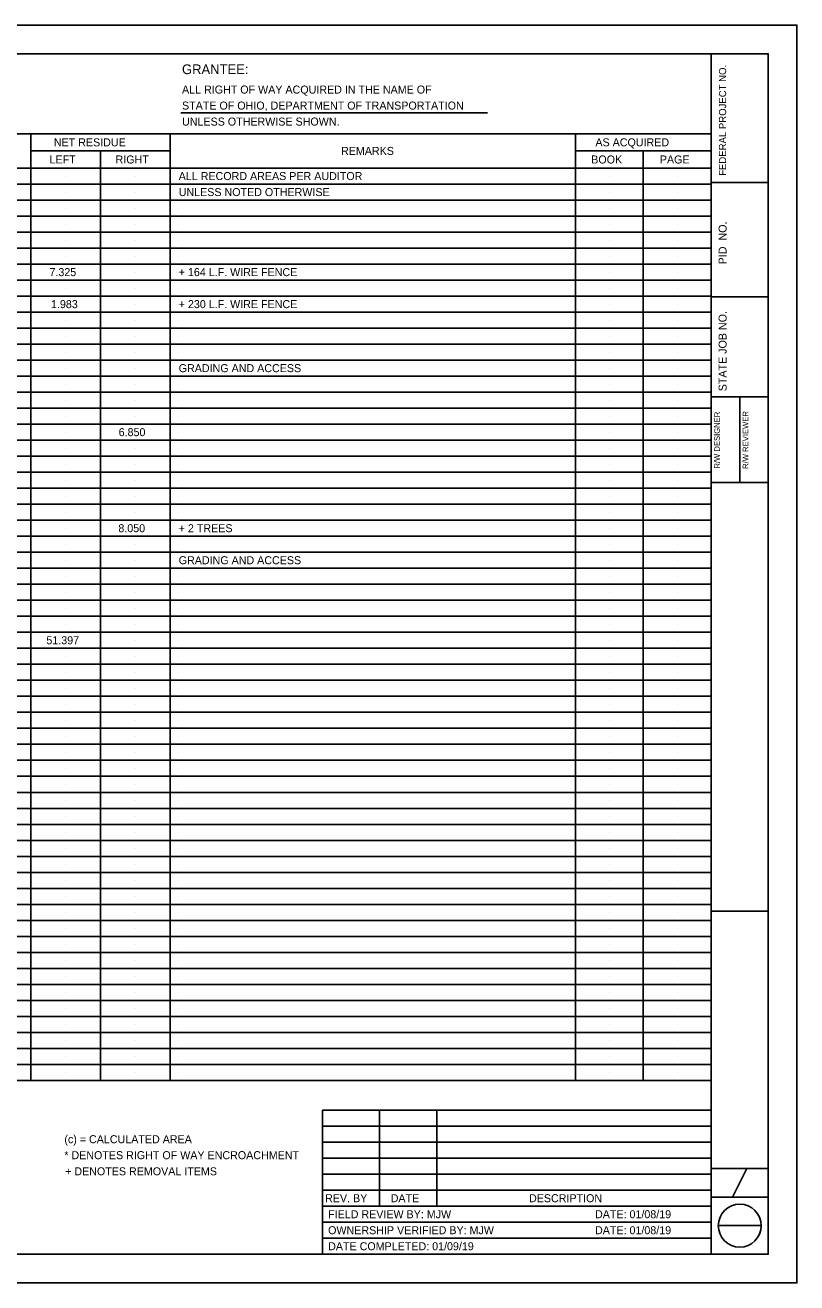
# Model space of a CAD drawing. Extents: x 1.1 to 35.1, y -0.9 to 21.1.
# Drawn here: x 21.58 to 35.08, y -0.86 to 21.14 of the extents above; entities that cross this region are included whole.
import ezdxf

# ---------------------------------------------------------------- set-up
doc = ezdxf.new("R2010")
doc.units = 0
for name, color, linetype in [('SH_Border', 7, 'Continuous'), ('SH_Cut_Line', 7, 'Continuous'), ('SH_Data', 7, 'Continuous'), ('SH_Text', 7, 'Continuous')]:
    doc.layers.add(name, color=color, linetype=linetype)

msp = doc.modelspace()

# ---------------------------------------------------------------- linework, layer by layer
at = {"layer": 'SH_Border'}
for p, q in [((33.585, -0.356), (33.585, 20.644)), ((33.585, 18.394), (34.585, 18.394)), ((33.585, 16.394), (34.585, 16.394)), ((33.585, 14.644), (34.585, 14.644)), ((34.085, 14.644), (34.085, 13.144)), ((33.585, 13.144), (34.585, 13.144)), ((33.585, 5.644), (34.585, 5.644)), ((33.585, 1.144), (34.585, 1.144)), ((34.21, 1.144), (33.96, 0.644)), ((33.585, 0.644), (34.585, 0.644))]:
    msp.add_line(p, q, dxfattribs=at)
msp.add_lwpolyline([(3.085, 20.644), (34.585, 20.644), (34.585, -0.356), (3.085, -0.356)], close=True, dxfattribs=at)
at = {"layer": 'SH_Cut_Line'}
msp.add_lwpolyline([(1.085, -0.856), (35.085, -0.856), (35.085, 21.144), (1.085, 21.144)], close=True, dxfattribs=at)
at = {"layer": 'SH_Data'}
for p, q in [((3.085, 19.244), (33.585, 19.244)), ((21.678, 19.244), (21.678, 2.684)), ((24.116, 19.244), (24.116, 2.684)), ((31.209, 19.244), (31.209, 2.684)), ((21.678, 18.944), (24.116, 18.944)), ((22.897, 18.944), (22.897, 2.684)), ((31.209, 18.944), (33.585, 18.944)), ((32.397, 18.944), (32.397, 2.684)), ((3.085, 18.644), (33.585, 18.644)), ((22.288, 18.504), (22.288, 18.504)), ((23.506, 18.504), (23.506, 18.504)), ((24.266, 18.504), (24.266, 18.504)), ((31.803, 18.504), (31.803, 18.504)), ((32.991, 18.504), (32.991, 18.504)), ((3.085, 18.364), (33.585, 18.364)), ((3.085, 18.084), (33.585, 18.084)), ((22.288, 18.224), (22.288, 18.224)), ((23.506, 18.224), (23.506, 18.224)), ((24.266, 18.224), (24.266, 18.224)), ((31.803, 18.224), (31.803, 18.224)), ((32.991, 18.224), (32.991, 18.224)), ((22.288, 17.944), (22.288, 17.944)), ((23.506, 17.944), (23.506, 17.944)), ((24.266, 17.944), (24.266, 17.944)), ((31.803, 17.944), (31.803, 17.944)), ((32.991, 17.944), (32.991, 17.944)), ((3.085, 17.804), (33.585, 17.804)), ((22.288, 17.664), (22.288, 17.664)), ((23.506, 17.664), (23.506, 17.664)), ((24.266, 17.664), (24.266, 17.664)), ((31.803, 17.664), (31.803, 17.664)), ((32.991, 17.664), (32.991, 17.664)), ((3.085, 17.524), (33.585, 17.524)), ((22.288, 17.384), (22.288, 17.384)), ((23.506, 17.384), (23.506, 17.384)), ((24.266, 17.384), (24.266, 17.384)), ((31.803, 17.384), (31.803, 17.384)), ((32.991, 17.384), (32.991, 17.384)), ((3.085, 17.244), (33.585, 17.244)), ((3.085, 16.964), (33.585, 16.964)), ((22.288, 17.104), (22.288, 17.104)), ((23.506, 17.104), (23.506, 17.104)), ((24.266, 17.104), (24.266, 17.104)), ((31.803, 17.104), (31.803, 17.104)), ((32.991, 17.104), (32.991, 17.104)), ((22.288, 16.824), (22.288, 16.824)), ((23.506, 16.824), (23.506, 16.824)), ((24.266, 16.824), (24.266, 16.824)), ((31.803, 16.824), (31.803, 16.824)), ((32.991, 16.824), (32.991, 16.824)), ((3.085, 16.684), (33.585, 16.684)), ((22.288, 16.544), (22.288, 16.544)), ((23.506, 16.544), (23.506, 16.544)), ((24.266, 16.544), (24.266, 16.544)), ((31.803, 16.544), (31.803, 16.544)), ((32.991, 16.544), (32.991, 16.544)), ((3.085, 16.404), (33.585, 16.404)), ((3.085, 16.124), (33.585, 16.124)), ((22.288, 16.264), (22.288, 16.264)), ((23.506, 16.264), (23.506, 16.264)), ((24.266, 16.264), (24.266, 16.264)), ((31.803, 16.264), (31.803, 16.264)), ((32.991, 16.264), (32.991, 16.264)), ((3.085, 15.844), (33.585, 15.844)), ((22.288, 15.984), (22.288, 15.984)), ((23.506, 15.984), (23.506, 15.984)), ((24.266, 15.984), (24.266, 15.984)), ((31.803, 15.984), (31.803, 15.984)), ((32.991, 15.984), (32.991, 15.984)), ((22.288, 15.704), (22.288, 15.704)), ((23.506, 15.704), (23.506, 15.704)), ((24.266, 15.704), (24.266, 15.704)), ((31.803, 15.704), (31.803, 15.704)), ((32.991, 15.704), (32.991, 15.704)), ((3.085, 15.564), (33.585, 15.564)), ((22.288, 15.424), (22.288, 15.424)), ((23.506, 15.424), (23.506, 15.424)), ((24.266, 15.424), (24.266, 15.424)), ((31.803, 15.424), (31.803, 15.424)), ((32.991, 15.424), (32.991, 15.424)), ((3.085, 15.284), (33.585, 15.284)), ((3.085, 15.004), (33.585, 15.004)), ((22.288, 15.144), (22.288, 15.144)), ((23.506, 15.144), (23.506, 15.144)), ((24.266, 15.144), (24.266, 15.144)), ((31.803, 15.144), (31.803, 15.144)), ((32.991, 15.144), (32.991, 15.144)), ((22.288, 14.864), (22.288, 14.864)), ((23.506, 14.864), (23.506, 14.864)), ((24.266, 14.864), (24.266, 14.864)), ((31.803, 14.864), (31.803, 14.864)), ((32.991, 14.864), (32.991, 14.864)), ((3.085, 14.724), (33.585, 14.724)), ((22.288, 14.584), (22.288, 14.584)), ((23.506, 14.584), (23.506, 14.584)), ((24.266, 14.584), (24.266, 14.584)), ((31.803, 14.584), (31.803, 14.584)), ((32.991, 14.584), (32.991, 14.584)), ((3.085, 14.444), (33.585, 14.444)), ((22.288, 14.304), (22.288, 14.304)), ((23.506, 14.304), (23.506, 14.304)), ((24.266, 14.304), (24.266, 14.304)), ((31.803, 14.304), (31.803, 14.304)), ((32.991, 14.304), (32.991, 14.304)), ((3.085, 14.164), (33.585, 14.164)), ((3.085, 13.884), (33.585, 13.884)), ((22.288, 14.024), (22.288, 14.024)), ((23.506, 14.024), (23.506, 14.024)), ((24.266, 14.024), (24.266, 14.024)), ((31.803, 14.024), (31.803, 14.024)), ((32.991, 14.024), (32.991, 14.024)), ((22.288, 13.744), (22.288, 13.744)), ((23.506, 13.744), (23.506, 13.744)), ((24.266, 13.744), (24.266, 13.744)), ((31.803, 13.744), (31.803, 13.744)), ((32.991, 13.744), (32.991, 13.744)), ((3.085, 13.604), (33.585, 13.604)), ((22.288, 13.464), (22.288, 13.464)), ((23.506, 13.464), (23.506, 13.464)), ((24.266, 13.464), (24.266, 13.464)), ((31.803, 13.464), (31.803, 13.464)), ((32.991, 13.464), (32.991, 13.464)), ((3.085, 13.324), (33.585, 13.324)), ((3.085, 13.044), (33.585, 13.044)), ((22.288, 13.184), (22.288, 13.184)), ((23.506, 13.184), (23.506, 13.184)), ((24.266, 13.184), (24.266, 13.184)), ((31.803, 13.184), (31.803, 13.184)), ((32.991, 13.184), (32.991, 13.184)), ((3.085, 12.764), (33.585, 12.764)), ((22.288, 12.904), (22.288, 12.904)), ((23.506, 12.904), (23.506, 12.904)), ((24.266, 12.904), (24.266, 12.904)), ((31.803, 12.904), (31.803, 12.904)), ((32.991, 12.904), (32.991, 12.904)), ((22.288, 12.624), (22.288, 12.624)), ((23.506, 12.624), (23.506, 12.624)), ((24.266, 12.624), (24.266, 12.624)), ((31.803, 12.624), (31.803, 12.624)), ((32.991, 12.624), (32.991, 12.624)), ((3.085, 12.484), (33.585, 12.484)), ((22.288, 12.344), (22.288, 12.344)), ((23.506, 12.344), (23.506, 12.344)), ((24.266, 12.344), (24.266, 12.344)), ((31.803, 12.344), (31.803, 12.344)), ((32.991, 12.344), (32.991, 12.344)), ((3.085, 12.204), (33.585, 12.204)), ((3.085, 11.924), (33.585, 11.924)), ((22.288, 12.064), (22.288, 12.064)), ((23.506, 12.064), (23.506, 12.064)), ((24.266, 12.064), (24.266, 12.064)), ((31.803, 12.064), (31.803, 12.064)), ((32.991, 12.064), (32.991, 12.064)), ((22.288, 11.784), (22.288, 11.784)), ((23.506, 11.784), (23.506, 11.784)), ((24.266, 11.784), (24.266, 11.784)), ((31.803, 11.784), (31.803, 11.784)), ((32.991, 11.784), (32.991, 11.784)), ((3.085, 11.644), (33.585, 11.644)), ((22.288, 11.504), (22.288, 11.504)), ((23.506, 11.504), (23.506, 11.504)), ((24.266, 11.504), (24.266, 11.504)), ((31.803, 11.504), (31.803, 11.504)), ((32.991, 11.504), (32.991, 11.504)), ((3.085, 11.364), (33.585, 11.364)), ((22.288, 11.224), (22.288, 11.224)), ((23.506, 11.224), (23.506, 11.224)), ((24.266, 11.224), (24.266, 11.224)), ((31.803, 11.224), (31.803, 11.224)), ((32.991, 11.224), (32.991, 11.224)), ((3.085, 11.084), (33.585, 11.084)), ((3.085, 10.804), (33.585, 10.804)), ((22.288, 10.944), (22.288, 10.944)), ((23.506, 10.944), (23.506, 10.944)), ((24.266, 10.944), (24.266, 10.944)), ((31.803, 10.944), (31.803, 10.944)), ((32.991, 10.944), (32.991, 10.944)), ((22.288, 10.664), (22.288, 10.664)), ((23.506, 10.664), (23.506, 10.664)), ((24.266, 10.664), (24.266, 10.664)), ((31.803, 10.664), (31.803, 10.664)), ((32.991, 10.664), (32.991, 10.664)), ((3.085, 10.524), (33.585, 10.524)), ((22.288, 10.384), (22.288, 10.384)), ((23.506, 10.384), (23.506, 10.384)), ((24.266, 10.384), (24.266, 10.384)), ((31.803, 10.384), (31.803, 10.384)), ((32.991, 10.384), (32.991, 10.384)), ((3.085, 10.244), (33.585, 10.244)), ((3.085, 9.964), (33.585, 9.964)), ((22.288, 10.104), (22.288, 10.104)), ((23.506, 10.104), (23.506, 10.104)), ((24.266, 10.104), (24.266, 10.104)), ((31.803, 10.104), (31.803, 10.104)), ((32.991, 10.104), (32.991, 10.104)), ((3.085, 9.684), (33.585, 9.684)), ((22.288, 9.824), (22.288, 9.824)), ((23.506, 9.824), (23.506, 9.824)), ((24.266, 9.824), (24.266, 9.824)), ((31.803, 9.824), (31.803, 9.824)), ((32.991, 9.824), (32.991, 9.824)), ((22.288, 9.544), (22.288, 9.544)), ((23.506, 9.544), (23.506, 9.544)), ((24.266, 9.544), (24.266, 9.544)), ((31.803, 9.544), (31.803, 9.544)), ((32.991, 9.544), (32.991, 9.544)), ((3.085, 9.404), (33.585, 9.404)), ((22.288, 9.264), (22.288, 9.264)), ((23.506, 9.264), (23.506, 9.264)), ((24.266, 9.264), (24.266, 9.264)), ((31.803, 9.264), (31.803, 9.264)), ((32.991, 9.264), (32.991, 9.264)), ((3.085, 9.124), (33.585, 9.124)), ((3.085, 8.844), (33.585, 8.844)), ((22.288, 8.984), (22.288, 8.984)), ((23.506, 8.984), (23.506, 8.984)), ((24.266, 8.984), (24.266, 8.984)), ((31.803, 8.984), (31.803, 8.984)), ((32.991, 8.984), (32.991, 8.984)), ((22.288, 8.704), (22.288, 8.704)), ((23.506, 8.704), (23.506, 8.704)), ((24.266, 8.704), (24.266, 8.704)), ((31.803, 8.704), (31.803, 8.704)), ((32.991, 8.704), (32.991, 8.704)), ((3.085, 8.564), (33.585, 8.564)), ((22.288, 8.424), (22.288, 8.424)), ((23.506, 8.424), (23.506, 8.424)), ((24.266, 8.424), (24.266, 8.424)), ((31.803, 8.424), (31.803, 8.424)), ((32.991, 8.424), (32.991, 8.424)), ((3.085, 8.284), (33.585, 8.284)), ((22.288, 8.144), (22.288, 8.144)), ((23.506, 8.144), (23.506, 8.144)), ((24.266, 8.144), (24.266, 8.144)), ((31.803, 8.144), (31.803, 8.144)), ((32.991, 8.144), (32.991, 8.144)), ((3.085, 8.004), (33.585, 8.004)), ((3.085, 7.724), (33.585, 7.724)), ((22.288, 7.864), (22.288, 7.864)), ((23.506, 7.864), (23.506, 7.864)), ((24.266, 7.864), (24.266, 7.864)), ((31.803, 7.864), (31.803, 7.864)), ((32.991, 7.864), (32.991, 7.864)), ((22.288, 7.584), (22.288, 7.584)), ((23.506, 7.584), (23.506, 7.584)), ((24.266, 7.584), (24.266, 7.584)), ((31.803, 7.584), (31.803, 7.584)), ((32.991, 7.584), (32.991, 7.584)), ((3.085, 7.444), (33.585, 7.444)), ((22.288, 7.304), (22.288, 7.304)), ((23.506, 7.304), (23.506, 7.304)), ((24.266, 7.304), (24.266, 7.304)), ((31.803, 7.304), (31.803, 7.304)), ((32.991, 7.304), (32.991, 7.304)), ((3.085, 7.164), (33.585, 7.164)), ((3.085, 6.884), (33.585, 6.884)), ((22.288, 7.024), (22.288, 7.024)), ((23.506, 7.024), (23.506, 7.024)), ((24.266, 7.024), (24.266, 7.024)), ((31.803, 7.024), (31.803, 7.024)), ((32.991, 7.024), (32.991, 7.024)), ((3.085, 6.604), (33.585, 6.604)), ((22.288, 6.744), (22.288, 6.744)), ((23.506, 6.744), (23.506, 6.744)), ((24.266, 6.744), (24.266, 6.744)), ((31.803, 6.744), (31.803, 6.744)), ((32.991, 6.744), (32.991, 6.744)), ((22.288, 6.464), (22.288, 6.464)), ((23.506, 6.464), (23.506, 6.464)), ((24.266, 6.464), (24.266, 6.464)), ((31.803, 6.464), (31.803, 6.464)), ((32.991, 6.464), (32.991, 6.464)), ((3.085, 6.324), (33.585, 6.324)), ((22.288, 6.184), (22.288, 6.184)), ((23.506, 6.184), (23.506, 6.184)), ((24.266, 6.184), (24.266, 6.184)), ((31.803, 6.184), (31.803, 6.184)), ((32.991, 6.184), (32.991, 6.184)), ((3.085, 6.044), (33.585, 6.044)), ((3.085, 5.764), (33.585, 5.764)), ((22.288, 5.904), (22.288, 5.904)), ((23.506, 5.904), (23.506, 5.904)), ((24.266, 5.904), (24.266, 5.904)), ((31.803, 5.904), (31.803, 5.904)), ((32.991, 5.904), (32.991, 5.904)), ((22.288, 5.624), (22.288, 5.624)), ((23.506, 5.624), (23.506, 5.624)), ((24.266, 5.624), (24.266, 5.624)), ((31.803, 5.624), (31.803, 5.624)), ((32.991, 5.624), (32.991, 5.624)), ((3.085, 5.484), (33.585, 5.484)), ((22.288, 5.344), (22.288, 5.344)), ((23.506, 5.344), (23.506, 5.344)), ((24.266, 5.344), (24.266, 5.344)), ((31.803, 5.344), (31.803, 5.344)), ((32.991, 5.344), (32.991, 5.344)), ((3.085, 5.204), (33.585, 5.204)), ((22.288, 5.064), (22.288, 5.064)), ((23.506, 5.064), (23.506, 5.064)), ((24.266, 5.064), (24.266, 5.064)), ((31.803, 5.064), (31.803, 5.064)), ((32.991, 5.064), (32.991, 5.064)), ((3.085, 4.924), (33.585, 4.924)), ((3.085, 4.644), (33.585, 4.644)), ((22.288, 4.784), (22.288, 4.784)), ((23.506, 4.784), (23.506, 4.784)), ((24.266, 4.784), (24.266, 4.784)), ((31.803, 4.784), (31.803, 4.784)), ((32.991, 4.784), (32.991, 4.784)), ((22.288, 4.504), (22.288, 4.504)), ((23.506, 4.504), (23.506, 4.504)), ((24.266, 4.504), (24.266, 4.504)), ((31.803, 4.504), (31.803, 4.504)), ((32.991, 4.504), (32.991, 4.504)), ((3.085, 4.364), (33.585, 4.364)), ((22.288, 4.224), (22.288, 4.224)), ((23.506, 4.224), (23.506, 4.224)), ((24.266, 4.224), (24.266, 4.224)), ((31.803, 4.224), (31.803, 4.224)), ((32.991, 4.224), (32.991, 4.224)), ((3.085, 4.084), (33.585, 4.084)), ((3.085, 3.804), (33.585, 3.804)), ((22.288, 3.944), (22.288, 3.944)), ((23.506, 3.944), (23.506, 3.944)), ((24.266, 3.944), (24.266, 3.944)), ((31.803, 3.944), (31.803, 3.944)), ((32.991, 3.944), (32.991, 3.944)), ((3.085, 3.524), (33.585, 3.524)), ((22.288, 3.664), (22.288, 3.664)), ((23.506, 3.664), (23.506, 3.664)), ((24.266, 3.664), (24.266, 3.664)), ((31.803, 3.664), (31.803, 3.664)), ((32.991, 3.664), (32.991, 3.664)), ((22.288, 3.384), (22.288, 3.384)), ((23.506, 3.384), (23.506, 3.384)), ((24.266, 3.384), (24.266, 3.384)), ((31.803, 3.384), (31.803, 3.384)), ((32.991, 3.384), (32.991, 3.384)), ((3.085, 3.244), (33.585, 3.244)), ((22.288, 3.104), (22.288, 3.104)), ((23.506, 3.104), (23.506, 3.104)), ((24.266, 3.104), (24.266, 3.104)), ((31.803, 3.104), (31.803, 3.104)), ((32.991, 3.104), (32.991, 3.104)), ((3.085, 2.964), (33.585, 2.964)), ((3.085, 2.684), (33.585, 2.684)), ((22.288, 2.824), (22.288, 2.824)), ((23.506, 2.824), (23.506, 2.824)), ((24.266, 2.824), (24.266, 2.824)), ((31.803, 2.824), (31.803, 2.824)), ((32.991, 2.824), (32.991, 2.824)), ((33.71, 0.144), (34.46, 0.144))]:
    msp.add_line(p, q, dxfattribs=at)
msp.add_circle((34.085, 0.144), 0.375, dxfattribs=at)
at = {"layer": 'SH_Text'}
for p, q in [((24.302, 19.61), (29.671, 19.61)), ((26.781, 2.164), (26.781, -0.356)), ((26.781, 2.164), (33.585, 2.164)), ((27.781, 2.164), (27.781, 0.484)), ((28.781, 2.164), (28.781, 0.484)), ((26.781, 1.884), (33.585, 1.884)), ((26.781, 1.604), (33.585, 1.604)), ((26.781, 1.324), (33.585, 1.324)), ((26.781, 1.044), (33.585, 1.044)), ((26.781, 0.764), (33.585, 0.764)), ((26.781, 0.484), (33.585, 0.484)), ((26.781, 0.204), (33.585, 0.204)), ((26.781, -0.076), (33.585, -0.076)), ((33.585, -0.356), (33.585, -0.356))]:
    msp.add_line(p, q, dxfattribs=at)

# ---------------------------------------------------------------- texts
at = {"layer": 'SH_Data'}
for s, height, p in [('FEDERAL PROJECT NO.', 0.125, (33.847, 18.508)), ('PID  NO.', 0.14, (33.855, 16.96)), ('STATE JOB NO.', 0.14, (33.855, 14.739)), ('R/W DESIGNER', 0.1, (33.737, 13.387)), ('R/W REVIEWER', 0.1, (34.237, 13.382))]:
    msp.add_text(s, height=height, rotation=90, dxfattribs=at).set_placement(p)
for s, p in [('NET RESIDUE', (22.081, 19.024)), ('AS ACQUIRED', (31.559, 19.024)), ('REMARKS', (27.107, 18.874)), ('LEFT', (22.006, 18.724)), ('RIGHT', (23.161, 18.724)), ('BOOK', (31.486, 18.724)), ('PAGE', (32.686, 18.724)), ('ALL RECORD AREAS PER AUDITOR', (24.266, 18.434)), ('UNLESS NOTED OTHERWISE', (24.266, 18.154)), ('7.325', (22.004, 16.754)), ('+ 164 L.F. WIRE FENCE', (24.266, 16.754)), ('1.983', (22.031, 16.194)), ('+ 230 L.F. WIRE FENCE', (24.266, 16.194)), ('GRADING AND ACCESS', (24.266, 15.074)), ('6.850', (23.215, 13.954)), ('8.050', (23.21, 12.274)), ('+ 2 TREES', (24.266, 12.274)), ('GRADING AND ACCESS', (24.266, 11.714)), ('51.397', (21.95, 10.314))]:
    msp.add_text(s, height=0.14, dxfattribs=at).set_placement(p)
at = {"layer": 'SH_Text'}
for s, height, p in [('GRANTEE:', 0.17, (24.324, 20.287)), ('ALL RIGHT OF WAY ACQUIRED IN THE NAME OF', 0.14, (24.324, 19.947)), ('STATE OF OHIO, DEPARTMENT OF TRANSPORTATION', 0.14, (24.324, 19.667)), ('UNLESS OTHERWISE SHOWN.', 0.14, (24.324, 19.387)), ('(c) = CALCULATED AREA', 0.14, (22.265, 1.586)), ('* DENOTES RIGHT OF WAY ENCROACHMENT', 0.14, (22.264, 1.307)), ('+ DENOTES REMOVAL ITEMS', 0.14, (22.278, 1.025)), ('REV. BY', 0.14, (26.828, 0.554)), ('DATE', 0.14, (27.976, 0.554)), ('DESCRIPTION', 0.14, (30.397, 0.554)), ('FIELD REVIEW BY: MJW', 0.14, (26.881, 0.274)), ('DATE: 01/08/19', 0.14, (31.552, 0.274)), ('OWNERSHIP VERIFIED BY: MJW', 0.14, (26.881, -0.006)), ('DATE: 01/08/19', 0.14, (31.552, -0.006)), ('DATE COMPLETED: 01/09/19', 0.14, (26.881, -0.286))]:
    msp.add_text(s, height=height, dxfattribs=at).set_placement(p)

doc.saveas('drawing.dxf')
